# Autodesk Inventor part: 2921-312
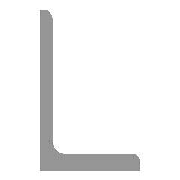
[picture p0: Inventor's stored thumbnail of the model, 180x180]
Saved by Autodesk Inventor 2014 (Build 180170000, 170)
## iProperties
IsCustomPart: 1
Company: NHTSA/VRTC
Created: 2012-02
Part Number: 2921-312
Material: Steel
Description: BENCH BASE MTG. ANGLE
Document SubType Name: Modeling
Standard: AISC
Designer: Mike Vanvoorhis
Standards Organization: ANSI
Language: en-US
Size Designation: L 3 x 2 x 3/8 - 19.21259843
Categories: <MemberInstance><Categories><Category DisplayName="Structural Shapes" InternalName="089c4875-fa83-4c05-b084-43b9cc11f5ed" Mnemonic="GRDR"><CategoryParameter Dis
Stock Number: L 3 x 2 x 3/8 x 19.213" (488.0mm)
Density: 7.85 g/cm^3
Project: CHILD SIDE IMPACT SLED
Mass: 3915.58 g
Surface Area: 1132.41 cm^2
Volume: 498.8 cm^3
Appearance: Steel
G_L: 19.213 in
Author: Dave Walker
Title: Bench Frame Mounting Plate
Subject: Side Impact Child Sled
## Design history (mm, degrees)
node "Start plane"
node "End plane"
sketch "Sketch"
  geometry: L1 (46.736, 9.525)-(17.399, 9.525); L2 (0, 0)-(50.8, 0); L3 (50.8, 0)-(50.8, 5.461); L4 (-7.041, 0)-(21.538, 0); L5 (9.525, 17.399)-(9.525, 72.136); L6 (0, 76.2)-(0, 0); L7 (5.461, 76.2)-(0, 76.2); L8 (0, -8.041)-(0, 34.538); L9 (0, 43.054)-(0, -16.557) reference; L10 (-12.757, 0)-(27.254, 0) reference; A1 r 7.874 centre (17.399, 17.399) between (9.525, 17.399) and (17.399, 9.525); A2 r 4.064 centre (46.736, 5.461) between (50.8, 5.461) and (46.736, 9.525); A3 r 4.064 centre (5.461, 72.136) between (9.525, 72.136) and (5.461, 76.2); 3 further points
  constraints: 16 end point, 6 point on circle, 6 point on line, 6 tangent, 3 centre point, 2 collinear, 2 parallel, 1 equal radius
  dimensions: "d12" = 9.525 distance between parallel lines of L5 L6 (= G_T); "d13" = 76.2 distance of L6.start L2.start (= G_H); "d14" = 50.8 distance of L2.start L2.end (= G_W); "d15" = 0 distance between parallel lines of L4 L2 (computed from ex); "d16" = 9.525 distance between parallel lines of L2 L1 (= G_T); "d17" = 0 distance between parallel lines of L8 L6 (computed from ey); "d18" = 7.874 radius of A1 (= G_IR); "d19" = 4.064 radius of A2 (= G_ER)
extrude "Body" new body sketch "Sketch" stored distance "d4" = 488 (= G_L); taper "d5" = 0 deg
node "Driven Length"
  sketch "Sketch3"
    geometry: L1 (0, 0)-(10, 0) reference
    constraints: 2 end point, 1 horizontal
  workplane "Work Plane3"
  sketch "Sketch4"
    geometry: L1 (-2, 0)-(12, 0) reference; L2 (-2, 488)-(12, 488) reference
    dimensions: "d23" = 488 distance between parallel lines of L1 L2 (derived)
sketch "Sketch5"
  geometry: L1 (17.399, 9.525)-(46.736, 9.525) reference; L2 (0, 0)-(0, 76.2) reference; L3 (50.8, 5.461)-(50.8, 0) reference; L4 (40, 9.525)-(50.8, 9.525); L5 (50.8, 9.525)-(50.8, 0); L6 (50.8, 0)-(40, 0); L7 (40, 0)-(40, 9.525); A1 r 4.064 centre (46.736, 5.461) between (50.8, 5.461) and (46.736, 9.525) reference
  constraints: 8 end point, 2 parallel, 1 horizontal, 1 perpendicular, 1 point on line
  dimensions: "d24" = 40 distance between parallel lines of L7 L2
extrude "Extrusion2" cut sketch "Sketch5" stored distance "d25" = 25.4; taper "d26" = 0 deg
sketch "Sketch6"
  geometry: L1 (488, -76.2)-(488, 0) reference; L2 (0, -76.2)-(488, -76.2) reference; 2 further points
  constraints: 1 horizontal alignment
  dimensions: "d27" = 40 distance from line of point (443, -36.2) L2; "d28" = 45 distance from line of point (443, -36.2) L1; "d29" = 445 distance from line of point (43, -36.2) L1
hole "Hole1" sketch "Sketch6" at (443, -36.2), (43, -36.2) diameter "d30" = 11; stored, may be unused: countersink angle "d34" = 82 deg, drill point angle "d36" = 118 deg; dims "d31" = 19.05, "d32" = 9.525, "d33" = 6.35, "d35" = 25.4
body "Solid1"
other parameters: "G_W" = 50.8 [user parameter; used in 1 equation term], "G_H" = 76.2 [user parameter; used in 1 equation term], "G_T" = 9.525 [user parameter; used in 2 equation terms], "G_ER" = 4.064 [user parameter; used in 1 equation term], "G_IR" = 7.874 [user parameter; used in 1 equation term], "G_L" = 488 (= d23) [user parameter; used in 1 equation term], "ex" = 0 [user parameter; used in 1 equation term], "ey" = 0 [user parameter; used in 1 equation term], "G_OFFSET_START" = 0 [user parameter; used in 1 equation term], "G_OFFSET_END" = 0 [user parameter; used in 1 equation term], "d20" = 0 (computed from G_OFFSET_START), "d21" = 488 (= G_OFFSET_END + B_L), "B_L" = 488 [user parameter; used in 1 equation term], "d22" = 90 deg, "MAS" = 0.87802 [user parameter]
